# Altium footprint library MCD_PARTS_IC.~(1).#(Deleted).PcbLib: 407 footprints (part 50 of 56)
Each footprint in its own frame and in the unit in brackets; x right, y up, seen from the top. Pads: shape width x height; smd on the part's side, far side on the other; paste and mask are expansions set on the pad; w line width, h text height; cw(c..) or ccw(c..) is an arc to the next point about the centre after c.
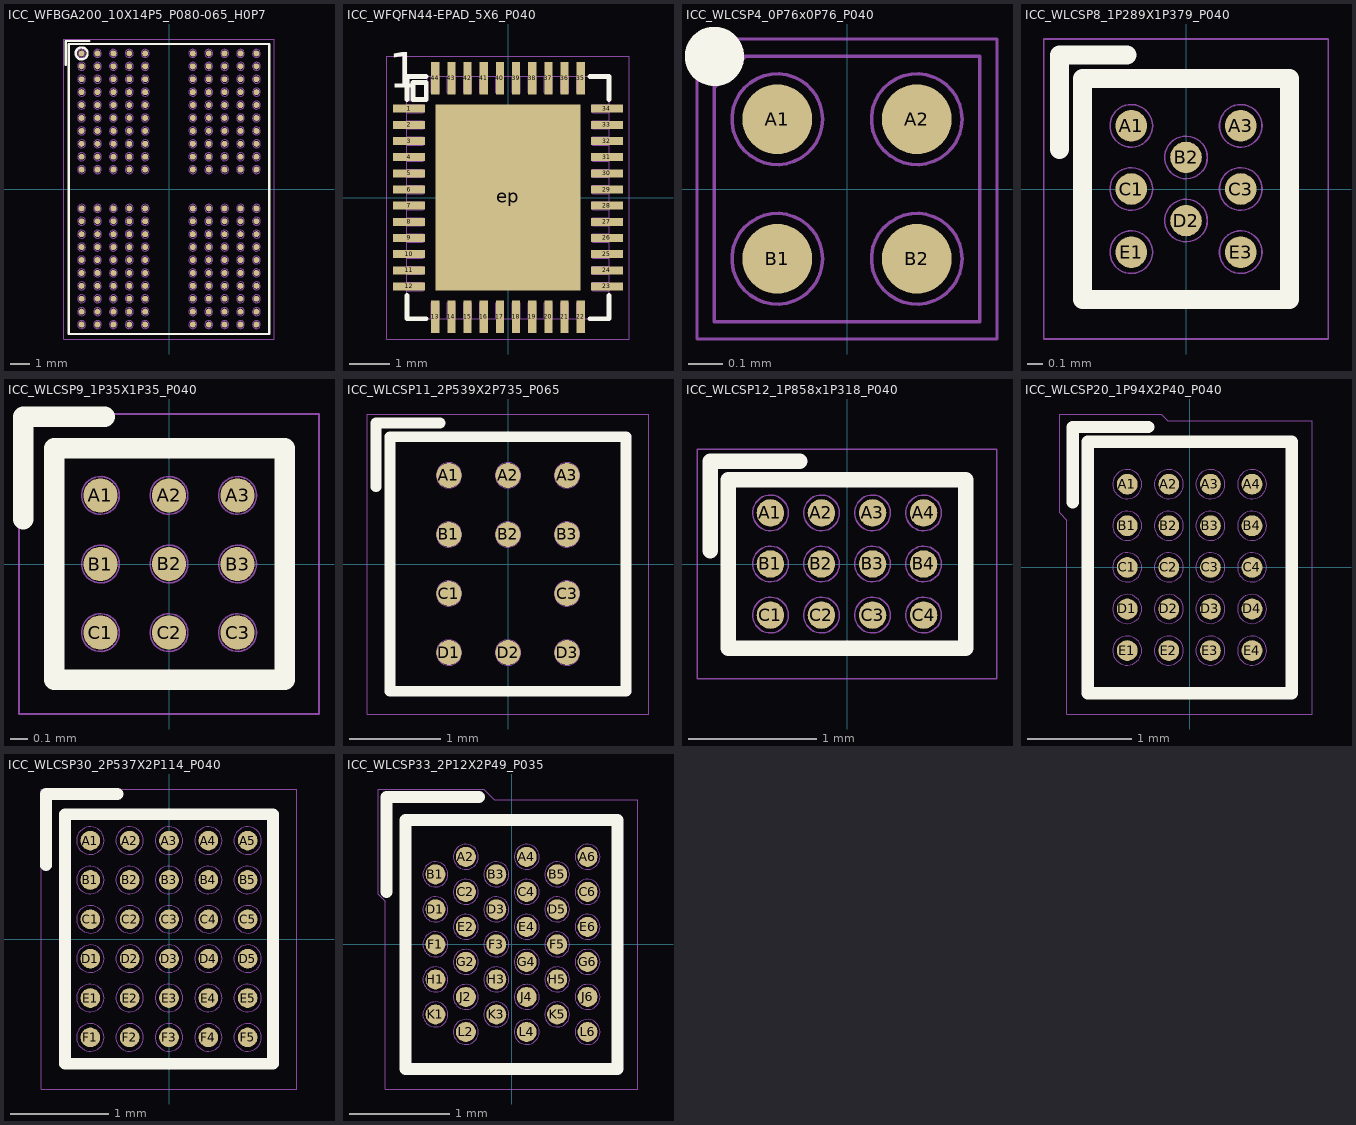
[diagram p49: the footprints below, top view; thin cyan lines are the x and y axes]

## ICC_WFBGA200_10X14P5_P080-065_H0P7 [mm] "MCD-02297"
height 0.8
pads (200):
  round 0.3 smd mask+0.05: A1(-4.4,6.825) A2(-3.6,6.825) A3(-2.8,6.825) A4(-2,6.825) A5(-1.2,6.825) A8(1.2,6.825) A9(2,6.825) A10(2.8,6.825) A11(3.6,6.825) A12(4.4,6.825) AA1(-4.4,-6.175) AA2(-3.6,-6.175) AA3(-2.8,-6.175) AA4(-2,-6.175) AA5(-1.2,-6.175) AA8(1.2,-6.175) AA9(2,-6.175) AA10(2.8,-6.175) AA11(3.6,-6.175) AA12(4.4,-6.175) AB1(-4.4,-6.825) AB2(-3.6,-6.825) AB3(-2.8,-6.825) AB4(-2,-6.825) AB5(-1.2,-6.825) AB8(1.2,-6.825) AB9(2,-6.825) AB10(2.8,-6.825) AB11(3.6,-6.825) AB12(4.4,-6.825) B1(-4.4,6.175) B2(-3.6,6.175) B3(-2.8,6.175) B4(-2,6.175) B5(-1.2,6.175) B8(1.2,6.175) B9(2,6.175) B10(2.8,6.175) B11(3.6,6.175) B12(4.4,6.175) C1(-4.4,5.525) C2(-3.6,5.525) C3(-2.8,5.525) C4(-2,5.525) C5(-1.2,5.525) C8(1.2,5.525) C9(2,5.525) C10(2.8,5.525) C11(3.6,5.525) C12(4.4,5.525) D1(-4.4,4.875) D2(-3.6,4.875) D3(-2.8,4.875) D4(-2,4.875) D5(-1.2,4.875) D8(1.2,4.875) D9(2,4.875) D10(2.8,4.875) D11(3.6,4.875) D12(4.4,4.875) E1(-4.4,4.225) E2(-3.6,4.225) E3(-2.8,4.225) E4(-2,4.225) E5(-1.2,4.225) E8(1.2,4.225) E9(2,4.225) E10(2.8,4.225) E11(3.6,4.225) E12(4.4,4.225) F1(-4.4,3.575) F2(-3.6,3.575) F3(-2.8,3.575) F4(-2,3.575) F5(-1.2,3.575) F8(1.2,3.575) F9(2,3.575) F10(2.8,3.575) F11(3.6,3.575) F12(4.4,3.575) G1(-4.4,2.925) G2(-3.6,2.925) G3(-2.8,2.925) G4(-2,2.925) G5(-1.2,2.925) G8(1.2,2.925) G9(2,2.925) G10(2.8,2.925) G11(3.6,2.925) G12(4.4,2.925) H1(-4.4,2.275) H2(-3.6,2.275) H3(-2.8,2.275) H4(-2,2.275) H5(-1.2,2.275) H8(1.2,2.275) H9(2,2.275) H10(2.8,2.275) H11(3.6,2.275) H12(4.4,2.275) J1(-4.4,1.625) J2(-3.6,1.625) J3(-2.8,1.625) J4(-2,1.625) J5(-1.2,1.625) J8(1.2,1.625) J9(2,1.625) J10(2.8,1.625) J11(3.6,1.625) J12(4.4,1.625) K1(-4.4,0.975) K2(-3.6,0.975) K3(-2.8,0.975) K4(-2,0.975) K5(-1.2,0.975) K8(1.2,0.975) K9(2,0.975) K10(2.8,0.975) K11(3.6,0.975) K12(4.4,0.975) N1(-4.4,-0.975) N2(-3.6,-0.975) N3(-2.8,-0.975) N4(-2,-0.975) N5(-1.2,-0.975) N8(1.2,-0.975) N9(2,-0.975) N10(2.8,-0.975) N11(3.6,-0.975) N12(4.4,-0.975) P1(-4.4,-1.625) P2(-3.6,-1.625) P3(-2.8,-1.625) P4(-2,-1.625) P5(-1.2,-1.625) P8(1.2,-1.625) P9(2,-1.625) P10(2.8,-1.625) P11(3.6,-1.625) P12(4.4,-1.625) R1(-4.4,-2.275) R2(-3.6,-2.275) R3(-2.8,-2.275) R4(-2,-2.275) R5(-1.2,-2.275) R8(1.2,-2.275) R9(2,-2.275) R10(2.8,-2.275) R11(3.6,-2.275) R12(4.4,-2.275) T1(-4.4,-2.925) T2(-3.6,-2.925) T3(-2.8,-2.925) T4(-2,-2.925) T5(-1.2,-2.925) T8(1.2,-2.925) T9(2,-2.925) T10(2.8,-2.925) T11(3.6,-2.925) T12(4.4,-2.925) U1(-4.4,-3.575) U2(-3.6,-3.575) U3(-2.8,-3.575) U4(-2,-3.575) U5(-1.2,-3.575) U8(1.2,-3.575) U9(2,-3.575) U10(2.8,-3.575) U11(3.6,-3.575) U12(4.4,-3.575) V1(-4.4,-4.225) V2(-3.6,-4.225) V3(-2.8,-4.225) V4(-2,-4.225) V5(-1.2,-4.225) V8(1.2,-4.225) V9(2,-4.225) V10(2.8,-4.225) V11(3.6,-4.225) V12(4.4,-4.225) W1(-4.4,-4.875) W2(-3.6,-4.875) W3(-2.8,-4.875) W4(-2,-4.875) W5(-1.2,-4.875) W8(1.2,-4.875) W9(2,-4.875) W10(2.8,-4.875) W11(3.6,-4.875) W12(4.4,-4.875) Y1(-4.4,-5.525) Y2(-3.6,-5.525) Y3(-2.8,-5.525) Y4(-2,-5.525) Y5(-1.2,-5.525) Y8(1.2,-5.525) Y9(2,-5.525) Y10(2.8,-5.525) Y11(3.6,-5.525) Y12(4.4,-5.525)
Top Overlay:
  circle w0.12: c-4.4,6.825 r0.3
  lines w0.12: -5.2,6.25 -5.2,7.45 -4,7.45 ; -5.05,-7.3 5.05,-7.3 5.05,7.3 -5.05,7.3 -5.05,-7.3
M14-Top Assembly:
  drawing of 204 lines, arcs and shapes, not listed
  text "A1" at -4.65,6.65 h0.4
  text "'.Designator'" at -2,-0.5 h0.75
  text "A8" at 0.875,6.65 h0.4
  text "A12" at 3.925,6.65 h0.4
  text "K1" at -4.625,0.8 h0.4
  text "K5" at -1.5,0.8 h0.4
  text "K8" at 0.875,0.8 h0.4
  text "K12" at 3.95,0.8 h0.4
  text "N1" at -4.65,-1.15 h0.4
  text "N5" at -1.525,-1.15 h0.4
  text "N8" at 0.875,-1.15 h0.4
  text "N12" at 3.925,-1.15 h0.4
  text "AB1" at -4.825,-7 h0.4
  text "AB5" at -1.7,-7 h0.4
  text "AB8" at 0.7,-7 h0.4
  text "AB12" at 3.675,-7 h0.4
  text "A5" at -1.525,6.65 h0.4
M16-Top Courtyard:
  lines w0.01: -5.3,-7.55 -5.3,7.55 5.3,7.55 5.3,-7.55 -5.3,-7.55
3D body: height 0.81, standoff 0.8, extent -4.697,6.526 -4.1,7.125
3D body: height 0.36, standoff -0.04, extent 4.201,-2.472 4.6,-2.078
3D body: height 0.36, standoff -0.04, extent 3.401,-2.472 3.8,-2.078
3D body: height 0.36, standoff -0.04, extent 1.001,-2.472 1.4,-2.078
3D body: height 0.36, standoff -0.04, extent 1.801,-2.472 2.2,-2.078
3D body: height 0.36, standoff -0.04, extent 2.601,-2.472 3,-2.078
3D body: height 0.36, standoff -0.04, extent -4.599,-2.472 -4.2,-2.078
3D body: height 0.36, standoff -0.04, extent -3.799,-2.472 -3.4,-2.078
3D body: height 0.36, standoff -0.04, extent -2.999,-2.472 -2.6,-2.078
3D body: height 0.36, standoff -0.04, extent -2.199,-2.472 -1.8,-2.078
3D body: height 0.36, standoff -0.04, extent -1.399,-2.472 -1,-2.078
3D body: height 0.36, standoff -0.04, extent 4.201,-1.822 4.6,-1.428
3D body: height 0.36, standoff -0.04, extent 3.401,-1.822 3.8,-1.428
3D body: height 0.36, standoff -0.04, extent 1.001,-1.822 1.4,-1.428
3D body: height 0.36, standoff -0.04, extent 1.801,-1.822 2.2,-1.428
3D body: height 0.36, standoff -0.04, extent 2.601,-1.822 3,-1.428
3D body: height 0.36, standoff -0.04, extent -4.599,-1.822 -4.2,-1.428
3D body: height 0.36, standoff -0.04, extent -3.799,-1.822 -3.4,-1.428
3D body: height 0.36, standoff -0.04, extent -2.999,-1.822 -2.6,-1.428
3D body: height 0.36, standoff -0.04, extent -2.199,-1.822 -1.8,-1.428
3D body: height 0.36, standoff -0.04, extent -1.399,-1.822 -1,-1.428
3D body: height 0.36, standoff -0.04, extent 4.201,-1.172 4.6,-0.778
3D body: height 0.36, standoff -0.04, extent 3.401,-1.172 3.8,-0.778
3D body: height 0.36, standoff -0.04, extent 1.001,-1.172 1.4,-0.778
3D body: height 0.36, standoff -0.04, extent 1.801,-1.172 2.2,-0.778
3D body: height 0.36, standoff -0.04, extent 2.601,-1.172 3,-0.778
3D body: height 0.36, standoff -0.04, extent -4.599,-1.172 -4.2,-0.778
3D body: height 0.36, standoff -0.04, extent -3.799,-1.172 -3.4,-0.778
3D body: height 0.36, standoff -0.04, extent -2.999,-1.172 -2.6,-0.778
3D body: height 0.36, standoff -0.04, extent -2.199,-1.172 -1.8,-0.778
3D body: height 0.36, standoff -0.04, extent -1.399,-1.172 -1,-0.778
3D body: height 0.36, standoff -0.04, extent 3.401,0.778 3.8,1.172
3D body: height 0.36, standoff -0.04, extent 1.001,0.778 1.4,1.172
3D body: height 0.36, standoff -0.04, extent 1.801,0.778 2.2,1.172
3D body: height 0.36, standoff -0.04, extent 2.601,0.778 3,1.172
3D body: height 0.36, standoff -0.04, extent -4.599,0.778 -4.2,1.172
3D body: height 0.36, standoff -0.04, extent -3.799,0.778 -3.4,1.172
3D body: height 0.36, standoff -0.04, extent -2.999,0.778 -2.6,1.172
3D body: height 0.36, standoff -0.04, extent -2.199,0.778 -1.8,1.172
3D body: height 0.36, standoff -0.04, extent -1.399,0.778 -1,1.172
3D body: height 0.36, standoff -0.04, extent 3.401,1.428 3.8,1.822
3D body: height 0.36, standoff -0.04, extent 1.001,1.428 1.4,1.822
3D body: height 0.36, standoff -0.04, extent 1.801,1.428 2.2,1.822
3D body: height 0.36, standoff -0.04, extent 2.601,1.428 3,1.822
3D body: height 0.36, standoff -0.04, extent -4.599,1.428 -4.2,1.822
3D body: height 0.36, standoff -0.04, extent -3.799,1.428 -3.4,1.822
3D body: height 0.36, standoff -0.04, extent -2.999,1.428 -2.6,1.822
3D body: height 0.36, standoff -0.04, extent -2.199,1.428 -1.8,1.822
3D body: height 0.36, standoff -0.04, extent -1.399,1.428 -1,1.822
3D body: height 0.36, standoff -0.04, extent 3.401,2.078 3.8,2.472
3D body: height 0.36, standoff -0.04, extent 1.001,2.078 1.4,2.472
3D body: height 0.36, standoff -0.04, extent 1.801,2.078 2.2,2.472
3D body: height 0.36, standoff -0.04, extent 2.601,2.078 3,2.472
3D body: height 0.36, standoff -0.04, extent -4.599,2.078 -4.2,2.472
3D body: height 0.36, standoff -0.04, extent -3.799,2.078 -3.4,2.472
3D body: height 0.36, standoff -0.04, extent -2.999,2.078 -2.6,2.472
3D body: height 0.36, standoff -0.04, extent -2.199,2.078 -1.8,2.472
3D body: height 0.36, standoff -0.04, extent -1.399,2.078 -1,2.472
3D body: height 0.36, standoff -0.04, extent 3.401,2.728 3.8,3.122
3D body: height 0.36, standoff -0.04, extent 1.001,2.728 1.4,3.122
3D body: height 0.36, standoff -0.04, extent 1.801,2.728 2.2,3.122
3D body: height 0.36, standoff -0.04, extent 2.601,2.728 3,3.122
3D body: height 0.36, standoff -0.04, extent -4.599,2.728 -4.2,3.122
3D body: height 0.36, standoff -0.04, extent -3.799,2.728 -3.4,3.122
3D body: height 0.36, standoff -0.04, extent -2.999,2.728 -2.6,3.122
3D body: height 0.36, standoff -0.04, extent -2.199,2.728 -1.8,3.122
3D body: height 0.36, standoff -0.04, extent -1.399,2.728 -1,3.122
3D body: height 0.36, standoff -0.04, extent -4.599,3.378 -4.2,3.772
3D body: height 0.36, standoff -0.04, extent -3.799,3.378 -3.4,3.772
3D body: height 0.36, standoff -0.04, extent -2.999,3.378 -2.6,3.772
3D body: height 0.36, standoff -0.04, extent -2.199,3.378 -1.8,3.772
3D body: height 0.36, standoff -0.04, extent -1.399,3.378 -1,3.772
3D body: height 0.36, standoff -0.04, extent 4.201,4.028 4.6,4.422
3D body: height 0.36, standoff -0.04, extent 3.401,4.028 3.8,4.422
3D body: height 0.36, standoff -0.04, extent 1.001,4.028 1.4,4.422
3D body: height 0.36, standoff -0.04, extent 1.801,4.028 2.2,4.422
3D body: height 0.36, standoff -0.04, extent 2.601,4.028 3,4.422
3D body: height 0.36, standoff -0.04, extent -4.599,4.028 -4.2,4.422
3D body: height 0.36, standoff -0.04, extent -3.799,4.028 -3.4,4.422
3D body: height 0.36, standoff -0.04, extent -2.999,4.028 -2.6,4.422
3D body: height 0.36, standoff -0.04, extent -2.199,4.028 -1.8,4.422
3D body: height 0.36, standoff -0.04, extent -1.399,4.028 -1,4.422
3D body: height 0.36, standoff -0.04, extent 4.201,4.678 4.6,5.072
3D body: height 0.36, standoff -0.04, extent 3.401,4.678 3.8,5.072
3D body: height 0.36, standoff -0.04, extent 1.001,4.678 1.4,5.072
3D body: height 0.36, standoff -0.04, extent 1.801,4.678 2.2,5.072
3D body: height 0.36, standoff -0.04, extent 2.601,4.678 3,5.072
3D body: height 0.36, standoff -0.04, extent -4.599,4.678 -4.2,5.072
3D body: height 0.36, standoff -0.04, extent -3.799,4.678 -3.4,5.072
3D body: height 0.36, standoff -0.04, extent -2.999,4.678 -2.6,5.072
3D body: height 0.36, standoff -0.04, extent -2.199,4.678 -1.8,5.072
3D body: height 0.36, standoff -0.04, extent -1.399,4.678 -1,5.072
3D body: height 0.36, standoff -0.04, extent 4.201,5.328 4.6,5.722
3D body: height 0.36, standoff -0.04, extent 3.401,5.328 3.8,5.722
3D body: height 0.36, standoff -0.04, extent 1.001,5.328 1.4,5.722
3D body: height 0.36, standoff -0.04, extent 1.801,5.328 2.2,5.722
3D body: height 0.36, standoff -0.04, extent 2.601,5.328 3,5.722
3D body: height 0.36, standoff -0.04, extent -4.599,5.328 -4.2,5.722
3D body: height 0.36, standoff -0.04, extent -3.799,5.328 -3.4,5.722
3D body: height 0.36, standoff -0.04, extent -2.999,5.328 -2.6,5.722
3D body: height 0.36, standoff -0.04, extent -2.199,5.328 -1.8,5.722
3D body: height 0.36, standoff -0.04, extent -1.399,5.328 -1,5.722
3D body: height 0.36, standoff -0.04, extent 4.201,5.978 4.6,6.372
3D body: height 0.36, standoff -0.04, extent 3.401,5.978 3.8,6.372
3D body: height 0.36, standoff -0.04, extent 1.001,5.978 1.4,6.372
3D body: height 0.36, standoff -0.04, extent 1.801,5.978 2.2,6.372
3D body: height 0.36, standoff -0.04, extent 2.601,5.978 3,6.372
3D body: height 0.36, standoff -0.04, extent -4.599,5.978 -4.2,6.372
3D body: height 0.36, standoff -0.04, extent -3.799,5.978 -3.4,6.372
3D body: height 0.36, standoff -0.04, extent -2.999,5.978 -2.6,6.372
3D body: height 0.36, standoff -0.04, extent -2.199,5.978 -1.8,6.372
3D body: height 0.36, standoff -0.04, extent -1.399,5.978 -1,6.372
3D body: height 0.36, standoff -0.04, extent -1.399,6.628 -1,7.022
3D body: height 0.36, standoff -0.04, extent -2.199,6.628 -1.8,7.022
3D body: height 0.36, standoff -0.04, extent -2.999,6.628 -2.6,7.022
3D body: height 0.36, standoff -0.04, extent -3.799,6.628 -3.4,7.022
3D body: height 0.36, standoff -0.04, extent -4.599,6.628 -4.2,7.022
3D body: height 0.36, standoff -0.04, extent 2.601,6.628 3,7.022
3D body: height 0.36, standoff -0.04, extent 1.801,6.628 2.2,7.022
3D body: height 0.36, standoff -0.04, extent 1.001,6.628 1.4,7.022
3D body: height 0.36, standoff -0.04, extent 3.401,6.628 3.8,7.022
3D body: height 0.36, standoff -0.04, extent 4.201,6.628 4.6,7.022
3D body: height 0.8, standoff 0.3, extent -5.05,-7.3 5.05,7.3
3D body: height 0.36, standoff -0.04, extent -1.399,-3.122 -1,-2.728
3D body: height 0.36, standoff -0.04, extent -2.199,-3.122 -1.8,-2.728
3D body: height 0.36, standoff -0.04, extent -2.999,-3.122 -2.6,-2.728
3D body: height 0.36, standoff -0.04, extent -3.799,-3.122 -3.4,-2.728
3D body: height 0.36, standoff -0.04, extent -4.599,-3.122 -4.2,-2.728
3D body: height 0.36, standoff -0.04, extent 2.601,-3.122 3,-2.728
3D body: height 0.36, standoff -0.04, extent 1.801,-3.122 2.2,-2.728
3D body: height 0.36, standoff -0.04, extent 1.001,-3.122 1.4,-2.728
3D body: height 0.36, standoff -0.04, extent 3.401,-3.122 3.8,-2.728
3D body: height 0.36, standoff -0.04, extent 4.201,-3.122 4.6,-2.728
3D body: height 0.36, standoff -0.04, extent -1.399,-3.772 -1,-3.378
3D body: height 0.36, standoff -0.04, extent -2.199,-3.772 -1.8,-3.378
3D body: height 0.36, standoff -0.04, extent -2.999,-3.772 -2.6,-3.378
3D body: height 0.36, standoff -0.04, extent -3.799,-3.772 -3.4,-3.378
3D body: height 0.36, standoff -0.04, extent -4.599,-3.772 -4.2,-3.378
3D body: height 0.36, standoff -0.04, extent 2.601,-3.772 3,-3.378
3D body: height 0.36, standoff -0.04, extent 1.801,-3.772 2.2,-3.378
3D body: height 0.36, standoff -0.04, extent 1.001,-3.772 1.4,-3.378
3D body: height 0.36, standoff -0.04, extent 3.401,-3.772 3.8,-3.378
3D body: height 0.36, standoff -0.04, extent 4.201,-3.772 4.6,-3.378
3D body: height 0.36, standoff -0.04, extent 4.201,3.378 4.6,3.772
3D body: height 0.36, standoff -0.04, extent 3.401,3.378 3.8,3.772
3D body: height 0.36, standoff -0.04, extent 1.001,3.378 1.4,3.772
3D body: height 0.36, standoff -0.04, extent 1.801,3.378 2.2,3.772
3D body: height 0.36, standoff -0.04, extent 2.601,3.378 3,3.772
3D body: height 0.36, standoff -0.04, extent 4.201,0.778 4.6,1.172
3D body: height 0.36, standoff -0.04, extent 4.201,1.428 4.6,1.822
3D body: height 0.36, standoff -0.04, extent 4.201,2.078 4.6,2.472
3D body: height 0.36, standoff -0.04, extent 4.201,2.728 4.6,3.122
3D body: height 0.36, standoff -0.04, extent -1.399,-4.422 -1,-4.028
3D body: height 0.36, standoff -0.04, extent -2.199,-4.422 -1.8,-4.028
3D body: height 0.36, standoff -0.04, extent -2.999,-4.422 -2.6,-4.028
3D body: height 0.36, standoff -0.04, extent -3.799,-4.422 -3.4,-4.028
3D body: height 0.36, standoff -0.04, extent -4.599,-4.422 -4.2,-4.028
3D body: height 0.36, standoff -0.04, extent 2.601,-4.422 3,-4.028
3D body: height 0.36, standoff -0.04, extent 1.801,-4.422 2.2,-4.028
3D body: height 0.36, standoff -0.04, extent 1.001,-4.422 1.4,-4.028
3D body: height 0.36, standoff -0.04, extent 3.401,-4.422 3.8,-4.028
3D body: height 0.36, standoff -0.04, extent 4.201,-4.422 4.6,-4.028
3D body: height 0.36, standoff -0.04, extent -1.399,-5.072 -1,-4.678
3D body: height 0.36, standoff -0.04, extent -2.199,-5.072 -1.8,-4.678
3D body: height 0.36, standoff -0.04, extent -2.999,-5.072 -2.6,-4.678
3D body: height 0.36, standoff -0.04, extent -3.799,-5.072 -3.4,-4.678
3D body: height 0.36, standoff -0.04, extent -4.599,-5.072 -4.2,-4.678
3D body: height 0.36, standoff -0.04, extent 2.601,-5.072 3,-4.678
3D body: height 0.36, standoff -0.04, extent 1.801,-5.072 2.2,-4.678
3D body: height 0.36, standoff -0.04, extent 1.001,-5.072 1.4,-4.678
3D body: height 0.36, standoff -0.04, extent 3.401,-5.072 3.8,-4.678
3D body: height 0.36, standoff -0.04, extent 4.201,-5.072 4.6,-4.678
3D body: height 0.36, standoff -0.04, extent -1.399,-5.722 -1,-5.328
3D body: height 0.36, standoff -0.04, extent -2.199,-5.722 -1.8,-5.328
3D body: height 0.36, standoff -0.04, extent -2.999,-5.722 -2.6,-5.328
3D body: height 0.36, standoff -0.04, extent -3.799,-5.722 -3.4,-5.328
3D body: height 0.36, standoff -0.04, extent -4.599,-5.722 -4.2,-5.328
3D body: height 0.36, standoff -0.04, extent 2.601,-5.722 3,-5.328
3D body: height 0.36, standoff -0.04, extent 1.801,-5.722 2.2,-5.328
3D body: height 0.36, standoff -0.04, extent 1.001,-5.722 1.4,-5.328
3D body: height 0.36, standoff -0.04, extent 3.401,-5.722 3.8,-5.328
3D body: height 0.36, standoff -0.04, extent 4.201,-5.722 4.6,-5.328
3D body: height 0.36, standoff -0.04, extent -1.399,-6.372 -1,-5.978
3D body: height 0.36, standoff -0.04, extent -2.199,-6.372 -1.8,-5.978
3D body: height 0.36, standoff -0.04, extent -2.999,-6.372 -2.6,-5.978
3D body: height 0.36, standoff -0.04, extent -3.799,-6.372 -3.4,-5.978
3D body: height 0.36, standoff -0.04, extent -4.599,-6.372 -4.2,-5.978
3D body: height 0.36, standoff -0.04, extent 2.601,-6.372 3,-5.978
3D body: height 0.36, standoff -0.04, extent 1.801,-6.372 2.2,-5.978
3D body: height 0.36, standoff -0.04, extent 1.001,-6.372 1.4,-5.978
3D body: height 0.36, standoff -0.04, extent 3.401,-6.372 3.8,-5.978
3D body: height 0.36, standoff -0.04, extent 4.201,-6.372 4.6,-5.978
3D body: height 0.36, standoff -0.04, extent -1.399,-7.022 -1,-6.628
3D body: height 0.36, standoff -0.04, extent -2.199,-7.022 -1.8,-6.628
3D body: height 0.36, standoff -0.04, extent -2.999,-7.022 -2.6,-6.628
3D body: height 0.36, standoff -0.04, extent -3.799,-7.022 -3.4,-6.628
3D body: height 0.36, standoff -0.04, extent -4.599,-7.022 -4.2,-6.628
3D body: height 0.36, standoff -0.04, extent 2.601,-7.022 3,-6.628
3D body: height 0.36, standoff -0.04, extent 1.801,-7.022 2.2,-6.628
3D body: height 0.36, standoff -0.04, extent 1.001,-7.022 1.4,-6.628
3D body: height 0.36, standoff -0.04, extent 3.401,-7.022 3.8,-6.628
3D body: height 0.36, standoff -0.04, extent 4.201,-7.022 4.6,-6.628

## ICC_WFQFN44-EPAD_5X6_P040 [mm]
height 0.8
pads (45):
  rect 0.8x0.2 smd mask+0.05: 1(-2.45,2.2) 2(-2.45,1.8) 3(-2.45,1.4) 4(-2.45,1) 5(-2.45,0.6) 6(-2.45,0.2) 7(-2.45,-0.2) 8(-2.45,-0.6) 9(-2.45,-1) 10(-2.45,-1.4) 11(-2.45,-1.8) 12(-2.45,-2.2) 23(2.45,-2.2) 24(2.45,-1.8) 25(2.45,-1.4) 26(2.45,-1) 27(2.45,-0.6) 28(2.45,-0.2) 29(2.45,0.2) 30(2.45,0.6) 31(2.45,1) 32(2.45,1.4) 33(2.45,1.8) 34(2.45,2.2)
  rect 0.2x0.8 smd mask+0.05: 13(-1.8,-2.95) 14(-1.4,-2.95) 15(-1,-2.95) 16(-0.6,-2.95) 17(-0.2,-2.95) 18(0.2,-2.95) 19(0.6,-2.95) 20(1,-2.95) 21(1.4,-2.95) 22(1.8,-2.95) 35(1.8,2.95) 36(1.4,2.95) 37(1,2.95) 38(0.6,2.95) 39(0.2,2.95) 40(-0.2,2.95) 41(-0.6,2.95) 42(-1,2.95) 43(-1.4,2.95) 44(-1.8,2.95)
  rect 3.6x4.6 smd paste-1.8 mask+0.05: ep(0,0)
Top Overlay:
  lines w0.12: -2.5,-2.425 -2.5,-3 -2.025,-3 ; -2.5,2.425 -2.5,3 -2.025,3 ; 2.025,-3 2.5,-3 2.5,-2.425 ; 2.025,3 2.5,3 2.5,2.425 ; -2.35,2.425 -2.025,2.425 -2.025,2.85 -2.35,2.85 -2.35,2.425
  text "1" at -2.95,2.425 h1.5
Top Paste:
  rectangle: 1.3,-2.2 1.7,-1.825
  rectangle: 1.3,-1.625 1.7,-1.25
  rectangle: 1.3,-1.05 1.7,-0.675
  rectangle: 1.3,-0.475 1.7,-0.1
  rectangle: 0.7,-0.475 1.1,-0.1
  rectangle: 0.7,-1.05 1.1,-0.675
  rectangle: 0.7,-1.625 1.1,-1.25
  rectangle: 0.7,-2.2 1.1,-1.825
  rectangle: 0.1,-0.475 0.5,-0.1
  rectangle: 0.1,-1.05 0.5,-0.675
  rectangle: 0.1,-1.625 0.5,-1.25
  rectangle: 0.1,-2.2 0.5,-1.825
  rectangle: -0.5,-2.2 -0.1,-1.825
  rectangle: -0.5,-1.625 -0.1,-1.25
  rectangle: -0.5,-1.05 -0.1,-0.675
  rectangle: -0.5,-0.475 -0.1,-0.1
  rectangle: -1.1,-0.475 -0.7,-0.1
  rectangle: -1.1,-1.05 -0.7,-0.675
  rectangle: -1.1,-1.625 -0.7,-1.25
  rectangle: -1.1,-2.2 -0.7,-1.825
  rectangle: -1.7,-0.475 -1.3,-0.1
  rectangle: -1.7,-1.05 -1.3,-0.675
  rectangle: -1.7,-1.625 -1.3,-1.25
  rectangle: -1.7,-2.2 -1.3,-1.825
  rectangle: 1.3,0.1 1.7,0.475
  rectangle: 1.3,0.675 1.7,1.05
  rectangle: 1.3,1.25 1.7,1.625
  rectangle: 1.3,1.825 1.7,2.2
  rectangle: 0.7,1.825 1.1,2.2
  rectangle: 0.7,1.25 1.1,1.625
  rectangle: 0.7,0.675 1.1,1.05
  rectangle: 0.7,0.1 1.1,0.475
  rectangle: 0.1,1.825 0.5,2.2
  rectangle: 0.1,1.25 0.5,1.625
  rectangle: 0.1,0.675 0.5,1.05
  rectangle: 0.1,0.1 0.5,0.475
  rectangle: -1.7,0.1 -1.3,0.475
  rectangle: -1.7,0.675 -1.3,1.05
  rectangle: -1.7,1.25 -1.3,1.625
  rectangle: -1.7,1.825 -1.3,2.2
  rectangle: -1.1,0.1 -0.7,0.475
  rectangle: -1.1,0.675 -0.7,1.05
  rectangle: -1.1,1.25 -0.7,1.625
  rectangle: -1.1,1.825 -0.7,2.2
  rectangle: -0.5,1.825 -0.1,2.2
  rectangle: -0.5,1.25 -0.1,1.625
  rectangle: -0.5,0.675 -0.1,1.05
  rectangle: -0.5,0.1 -0.1,0.475
M14-Top Assembly:
  lines w0.01: -2.5,-2.3 -2.1,-2.3 -2.1,-2.1 -2.5,-2.1 ; -2.5,-1.9 -2.1,-1.9 -2.1,-1.7 -2.5,-1.7 ; -2.5,-1.5 -2.1,-1.5 -2.1,-1.3 -2.5,-1.3 ; -2.5,-1.1 -2.1,-1.1 -2.1,-0.9 -2.5,-0.9 ; -2.5,-0.7 -2.1,-0.7 -2.1,-0.5 -2.5,-0.5 ; -2.5,-0.3 -2.1,-0.3 -2.1,-0.1 -2.5,-0.1 ; -2.5,0.1 -2.1,0.1 -2.1,0.3 -2.5,0.3 ; -2.5,0.5 -2.1,0.5 -2.1,0.7 -2.5,0.7 ; -2.5,0.9 -2.1,0.9 -2.1,1.1 -2.5,1.1 ; -2.5,1.3 -2.1,1.3 -2.1,1.5 -2.5,1.5 ; -2.5,1.7 -2.1,1.7 -2.1,1.9 -2.5,1.9 ; -2.5,2.1 -2.1,2.1 -2.1,2.3 -2.5,2.3 ; -1.9,-3 -1.9,-2.6 -1.7,-2.6 -1.7,-3 ; -1.9,3 -1.9,2.6 -1.7,2.6 -1.7,3 ; -1.5,-3 -1.5,-2.6 -1.3,-2.6 -1.3,-3 ; -1.5,3 -1.5,2.6 -1.3,2.6 -1.3,3 ; -1.1,-3 -1.1,-2.6 -0.9,-2.6 -0.9,-3 ; -1.1,3 -1.1,2.6 -0.9,2.6 -0.9,3 ; -0.7,-3 -0.7,-2.6 -0.5,-2.6 -0.5,-3 ; -0.7,3 -0.7,2.6 -0.5,2.6 -0.5,3 ; -0.3,-3 -0.3,-2.6 -0.1,-2.6 -0.1,-3 ; -0.3,3 -0.3,2.6 -0.1,2.6 -0.1,3 ; 0.1,-3 0.1,-2.6 0.3,-2.6 0.3,-3 ; 0.1,3 0.1,2.6 0.3,2.6 0.3,3 ; 0.5,-3 0.5,-2.6 0.7,-2.6 0.7,-3 ; 0.5,3 0.5,2.6 0.7,2.6 0.7,3 ; 0.9,-3 0.9,-2.6 1.1,-2.6 1.1,-3 ; 0.9,3 0.9,2.6 1.1,2.6 1.1,3 ; 1.3,-3 1.3,-2.6 1.5,-2.6 1.5,-3 ; 1.3,3 1.3,2.6 1.5,2.6 1.5,3 ; 1.7,-3 1.7,-2.6 1.9,-2.6 1.9,-3 ; 1.7,3 1.7,2.6 1.9,2.6 1.9,3 ; 2.5,-2.3 2.1,-2.3 2.1,-2.1 2.5,-2.1 ; 2.5,-1.9 2.1,-1.9 2.1,-1.7 2.5,-1.7 ; 2.5,-1.5 2.1,-1.5 2.1,-1.3 2.5,-1.3 ; 2.5,-1.1 2.1,-1.1 2.1,-0.9 2.5,-0.9 ; 2.5,-0.7 2.1,-0.7 2.1,-0.5 2.5,-0.5 ; 2.5,-0.3 2.1,-0.3 2.1,-0.1 2.5,-0.1 ; 2.5,0.1 2.1,0.1 2.1,0.3 2.5,0.3 ; 2.5,0.5 2.1,0.5 2.1,0.7 2.5,0.7 ; 2.5,0.9 2.1,0.9 2.1,1.1 2.5,1.1 ; 2.5,1.3 2.1,1.3 2.1,1.5 2.5,1.5 ; 2.5,1.7 2.1,1.7 2.1,1.9 2.5,1.9 ; 2.5,2.1 2.1,2.1 2.1,2.3 2.5,2.3 ; -2.5,-3 2.5,-3 2.5,3 -2.5,3 -2.5,-3 ; -2.45,2.4 -2.45,2.95 -2,2.95 -2,2.4 -2.45,2.4 ; -1.75,-2.25 -1.75,2 -1.5,2.25 1.75,2.25 1.75,-2.25 -1.75,-2.25
  text "'.Designator'" at -2,0.5 h0.75
  text "1" at -2.675,2.05 h0.5
  text "12" at -2.95,-2.375 h0.5
  text "13" at -2.02,-3.36 h0.5
  text "22" at 1.56,-3.36 h0.5
  text "23" at 2.525,-2.35 h0.5
  text "34" at 2.525,2.05 h0.5
  text "35" at 1.58,3.06 h0.5
  text "44" at -2.04,3.05 h0.5
  text "ep" at -0.7,-0.2 h1.5
M16-Top Courtyard:
  lines w0.01: -3,-3.5 -3,2.35 -3,3.5 3,3.5 3,-3.5 -2.975,-3.5 -3,-3.5
3D body: height 0.8, standoff 0.02, extent -2.5,-3 2.5,3
3D body: height 0.02, standoff 0, extent -2.5,2.1 -2.1,2.3
3D body: height 0.02, standoff 0, extent -2.5,1.7 -2.1,1.9
3D body: height 0.02, standoff 0, extent -2.5,1.3 -2.1,1.5
3D body: height 0.02, standoff 0, extent -2.5,0.9 -2.1,1.1
3D body: height 0.02, standoff 0, extent -2.5,0.5 -2.1,0.7
3D body: height 0.02, standoff 0, extent -2.5,0.1 -2.1,0.3
3D body: height 0.02, standoff 0, extent -2.5,-0.3 -2.1,-0.1
3D body: height 0.02, standoff 0, extent -2.5,-0.7 -2.1,-0.5
3D body: height 0.02, standoff 0, extent -2.5,-1.1 -2.1,-0.9
3D body: height 0.02, standoff 0, extent -2.5,-1.5 -2.1,-1.3
3D body: height 0.02, standoff 0, extent -2.5,-1.9 -2.1,-1.7
3D body: height 0.02, standoff 0, extent -2.5,-2.3 -2.1,-2.1
3D body: height 0.02, standoff 0, extent -1.9,-3 -1.7,-2.6
3D body: height 0.02, standoff 0, extent -1.5,-3 -1.3,-2.6
3D body: height 0.02, standoff 0, extent -1.1,-3 -0.9,-2.6
3D body: height 0.02, standoff 0, extent -0.7,-3 -0.5,-2.6
3D body: height 0.02, standoff 0, extent -0.3,-3 -0.1,-2.6
3D body: height 0.02, standoff 0, extent 0.1,-3 0.3,-2.6
3D body: height 0.02, standoff 0, extent 0.5,-3 0.7,-2.6
3D body: height 0.02, standoff 0, extent 0.9,-3 1.1,-2.6
3D body: height 0.02, standoff 0, extent 1.3,-3 1.5,-2.6
3D body: height 0.02, standoff 0, extent 1.7,-3 1.9,-2.6
3D body: height 0.02, standoff 0, extent 2.1,-2.3 2.5,-2.1
3D body: height 0.02, standoff 0, extent 2.1,-1.9 2.5,-1.7
3D body: height 0.02, standoff 0, extent 2.1,-1.5 2.5,-1.3
3D body: height 0.02, standoff 0, extent 2.1,-1.1 2.5,-0.9
3D body: height 0.02, standoff 0, extent 2.1,-0.7 2.5,-0.5
3D body: height 0.02, standoff 0, extent 2.1,-0.3 2.5,-0.1
3D body: height 0.02, standoff 0, extent 2.1,0.1 2.5,0.3
3D body: height 0.02, standoff 0, extent 2.1,0.5 2.5,0.7
3D body: height 0.02, standoff 0, extent 2.1,0.9 2.5,1.1
3D body: height 0.02, standoff 0, extent 2.1,1.3 2.5,1.5
3D body: height 0.02, standoff 0, extent 2.1,1.7 2.5,1.9
3D body: height 0.02, standoff 0, extent 2.1,2.1 2.5,2.3
3D body: height 0.02, standoff 0, extent 1.7,2.6 1.9,3
3D body: height 0.02, standoff 0, extent 1.3,2.6 1.5,3
3D body: height 0.02, standoff 0, extent 0.9,2.6 1.1,3
3D body: height 0.02, standoff 0, extent 0.5,2.6 0.7,3
3D body: height 0.02, standoff 0, extent 0.1,2.6 0.3,3
3D body: height 0.02, standoff 0, extent -0.3,2.6 -0.1,3
3D body: height 0.02, standoff 0, extent -0.7,2.6 -0.5,3
3D body: height 0.02, standoff 0, extent -1.1,2.6 -0.9,3
3D body: height 0.02, standoff 0, extent -1.5,2.6 -1.3,3
3D body: height 0.02, standoff 0, extent -1.9,2.6 -1.7,3
3D body: height 0.81, standoff 0.8, extent -2.45,2.4 -2,2.95
3D body: height 0.02, standoff 0, extent -1.725,-2.225 1.725,2.225

## ICC_WLCSP4_0P76x0P76_P040 [mm] "MCD-02423"
height 0.63
pads (4):
  round 0.2 smd mask+0.05: A1(-0.2,0.2) A2(0.2,0.2) B1(-0.2,-0.2) B2(0.2,-0.2)
Top Overlay:
  circle w0.12: c-0.38,0.38 r0.025
M14-Top Assembly:
  circle w0.01: c0.2,-0.2 r0.13
  circle w0.01: c-0.2,-0.2 r0.13
  circle w0.01: c-0.2,0.2 r0.13
  circle w0.01: c0.2,0.2 r0.13
  lines w0.01: -0.38,0.29 -0.29,0.38 ; -0.38,-0.38 0.38,-0.38 0.38,0.38 -0.38,0.38 -0.38,-0.38
  text "A1" at -0.315,0.135 h0.2
  text "'.Designator'" at -2,-0.5 h0.75
M16-Top Courtyard:
  lines w0.01: -0.43,-0.43 -0.43,0.43 0.43,0.43 0.43,-0.43 -0.43,-0.43
3D body: height 0.63, standoff 0.27, extent -0.38,-0.38 0.38,0.38
3D body: height 0.27, standoff -0.01, extent -0.331,0.062 -0.06,0.338
3D body: height 0.27, standoff -0.01, extent 0.069,0.062 0.34,0.338
3D body: height 0.27, standoff -0.01, extent -0.331,-0.338 -0.06,-0.062
3D body: height 0.27, standoff -0.01, extent 0.069,-0.338 0.34,-0.062

## ICC_WLCSP8_1P289X1P379_P040 [mm] "MCD-04444"
height 0.58
pads (8):
  round 0.2 smd mask+0.05: A1(-0.346,0.4) A3(0.346,0.4) B2(0,0.2) C1(-0.346,0) C3(0.346,0) D2(0,-0.2) E1(-0.346,-0.4) E3(0.346,-0.4)
Top Overlay:
  lines w0.12: -0.8,0.25 -0.8,0.85 -0.375,0.85 ; -0.654,-0.7 -0.654,0.7 0.654,0.7 0.654,-0.7 -0.654,-0.7
M14-Top Assembly:
  circle w0.01: c0.346,-0.4 r0.135
  circle w0.01: c0,-0.2 r0.135
  circle w0.01: c-0.346,-0.4 r0.135
  circle w0.01: c0.346,0 r0.135
  circle w0.01: c0,0.2 r0.135
  circle w0.01: c-0.346,0 r0.135
  circle w0.01: c0.346,0.4 r0.135
  circle w0.01: c-0.346,0.4 r0.135
  lines w0.01: -0.654,-0.7 0.654,-0.7 0.654,0.7 -0.654,0.7 -0.654,-0.7
  text "'.Designator'" at -2,-0.5 h0.75
  text "A1" at -0.625,0.25 h0.5
M16-Top Courtyard:
  lines w0.01: -0.9,-0.95 0.9,-0.95 0.9,0.95 -0.9,0.95 -0.9,-0.95
3D body: height 0.27, standoff 0, extent -0.482,-0.535 -0.211,-0.265
3D body: height 0.27, standoff 0, extent 0.211,-0.535 0.482,-0.265
3D body: height 0.27, standoff 0, extent 0.211,-0.135 0.482,0.135
3D body: height 0.27, standoff 0, extent -0.482,-0.135 -0.211,0.135
3D body: height 0.27, standoff 0, extent -0.135,0.065 0.135,0.335
3D body: height 0.59, standoff 0.58, extent -0.55,0.325 -0.25,0.625
3D body: height 0.58, standoff 0.19, extent -0.654,-0.7 0.654,0.7
3D body: height 0.27, standoff 0, extent -0.135,-0.335 0.135,-0.065
3D body: height 0.27, standoff 0, extent 0.211,0.265 0.482,0.535
3D body: height 0.27, standoff 0, extent -0.482,0.265 -0.211,0.535

## ICC_WLCSP9_1P35X1P35_P040 [mm] "MCD-02405"
height 0.66
pads (9):
  round 0.2 smd mask+0.05: A1(-0.4,0.4) A2(0,0.4) A3(0.4,0.4) B1(-0.4,0) B2(0,0) B3(0.4,0) C1(-0.4,-0.4) C2(0,-0.4) C3(0.4,-0.4)
Top Overlay:
  lines w0.12: -0.85,0.26 -0.85,0.86 -0.375,0.86 ; -0.67,-0.675 -0.67,0.675 0.675,0.675 0.675,-0.675 -0.67,-0.675
M14-Top Assembly:
  circle w0.01: c-0.4,0.4 r0.11
  circle w0.01: c0,0.4 r0.11
  circle w0.01: c0.4,0.4 r0.11
  circle w0.01: c-0.4,0 r0.11
  circle w0.01: c0,0 r0.11
  circle w0.01: c0.4,0 r0.11
  circle w0.01: c-0.4,-0.4 r0.11
  circle w0.01: c0,-0.4 r0.11
  circle w0.01: c0.4,-0.4 r0.11
  lines w0.01: -0.675,-0.675 -0.675,0.675 0.675,0.675 0.675,-0.675 -0.675,-0.675
  text "A1" at -0.67,0.28 h0.5
  text "'.Designator'" at -2,-0.5 h0.75
M16-Top Courtyard:
  lines w0.01: -0.875,-0.875 -0.875,0.875 0.875,0.875 0.875,-0.875 -0.875,-0.875
3D body: height 0.22, standoff 0, extent -0.503,0.292 -0.29,0.508
3D body: height 0.22, standoff 0, extent 0.297,0.292 0.51,0.509
3D body: height 0.22, standoff 0, extent -0.103,-0.108 0.11,0.109
3D body: height 0.55, standoff 0.22, extent -0.675,-0.675 0.675,0.675
3D body: height 0.56, standoff 0.55, extent -0.549,0.25 -0.25,0.55
3D body: height 0.22, standoff 0, extent -0.103,0.292 0.11,0.508
3D body: height 0.22, standoff 0, extent -0.503,-0.108 -0.29,0.109
3D body: height 0.22, standoff 0, extent 0.297,-0.108 0.51,0.109
3D body: height 0.22, standoff 0, extent 0.297,-0.508 0.51,-0.291
3D body: height 0.22, standoff 0, extent -0.103,-0.508 0.11,-0.291
3D body: height 0.22, standoff 0, extent -0.503,-0.508 -0.29,-0.291

## ICC_WLCSP11_2P539X2P735_P065 [mm] "MCD-02354"
height 0.6
pads (11):
  round 0.275 smd paste+0 mask+0.05: A1(-0.65,0.975) A2(0,0.975) A3(0.65,0.975) B1(-0.65,0.325) B2(0,0.325) B3(0.65,0.325) C1(-0.65,-0.325) C3(0.65,-0.325) D1(-0.65,-0.975) D2(0,-0.975) D3(0.65,-0.975)
Top Overlay:
  lines w0.12: -1.45,0.85 -1.45,1.55 -0.75,1.55 ; -1.3,-1.4 1.3,-1.4 1.3,1.4 -1.3,1.4 -1.3,-1.4
M14-Top Assembly:
  circle w0.01: c0.65,0.975 r0.14
  circle w0.01: c0,0.975 r0.14
  circle w0.01: c-0.65,0.975 r0.14
  circle w0.01: c-0.65,0.325 r0.14
  circle w0.01: c0,0.325 r0.14
  circle w0.01: c0.65,0.325 r0.14
  circle w0.01: c-0.65,-0.325 r0.14
  circle w0.01: c0.65,-0.325 r0.14
  circle w0.01: c-0.65,-0.975 r0.14
  circle w0.01: c0,-0.975 r0.14
  circle w0.01: c0.65,-0.975 r0.14
  lines w0.01: -1.3,-1.4 1.3,-1.4 1.3,1.4 -1.3,1.4 -1.3,-1.4
  text "'.Designator'" at -2,-0.5 h0.75
  text "A1" at -0.89,0.825 h0.5
M16-Top Courtyard:
  lines w0.01: -1.55,-1.65 1.55,-1.65 1.55,1.65 -1.55,1.65 -1.55,-1.65
3D body: height 0.6, standoff 0.2, extent -1.3,-1.4 1.3,1.4
3D body: height 0.26, standoff -0.02, extent 0.514,0.837 0.786,1.113
3D body: height 0.26, standoff -0.02, extent -0.136,0.837 0.136,1.113
3D body: height 0.61, standoff 0.6, extent -0.799,0.825 -0.5,1.125
3D body: height 0.26, standoff -0.02, extent -0.781,0.837 -0.51,1.113
3D body: height 0.26, standoff -0.02, extent -0.781,0.187 -0.51,0.463
3D body: height 0.26, standoff -0.02, extent -0.136,0.187 0.136,0.463
3D body: height 0.26, standoff -0.02, extent 0.514,0.187 0.786,0.463
3D body: height 0.26, standoff -0.02, extent -0.781,-0.463 -0.51,-0.187
3D body: height 0.26, standoff -0.02, extent 0.514,-0.463 0.786,-0.187
3D body: height 0.26, standoff -0.02, extent -0.781,-1.113 -0.51,-0.837
3D body: height 0.26, standoff -0.02, extent -0.136,-1.113 0.136,-0.837
3D body: height 0.26, standoff -0.02, extent 0.514,-1.113 0.786,-0.837

## ICC_WLCSP12_1P858x1P318_P040 [mm] "MCD-03166"
height 0.612
pads (12):
  round 0.215 smd paste+0 mask+0.04: A1(-0.6,0.4) A2(-0.2,0.4) A3(0.2,0.4) A4(0.6,0.4) B1(-0.6,0) B2(-0.2,0) B3(0.2,0) B4(0.6,0) C1(-0.6,-0.4) C2(-0.2,-0.4) C3(0.2,-0.4) C4(0.6,-0.4)
Top Overlay:
  lines w0.12: -1.07,0.105 -1.07,0.805 -0.37,0.805 ; -0.929,-0.659 -0.929,0.659 0.929,0.659 0.929,-0.659 -0.929,-0.659
M14-Top Assembly:
  circle w0.01: c0.2,0 r0.14
  circle w0.01: c-0.6,0.4 r0.14
  circle w0.01: c-0.6,0 r0.14
  circle w0.01: c-0.6,-0.4 r0.14
  circle w0.01: c-0.2,-0.4 r0.14
  circle w0.01: c-0.2,0 r0.14
  circle w0.01: c-0.2,0.4 r0.14
  circle w0.01: c0.2,-0.4 r0.14
  circle w0.01: c0.2,0.4 r0.14
  circle w0.01: c0.6,-0.4 r0.14
  circle w0.01: c0.6,0 r0.14
  circle w0.01: c0.6,0.4 r0.14
  lines w0.01: -0.929,-0.659 0.929,-0.659 0.929,0.659 -0.929,0.659 -0.929,-0.659
  text "'.Designator'" at -2,-0.5 h0.75
  text "A1" at -0.875,0.25 h0.5
M16-Top Courtyard:
  lines w0.01: -1.175,-0.9 -1.175,0.9 1.175,0.9 1.175,-0.9 -1.175,-0.9
3D body: height 0.26, standoff -0.02, extent 0.062,-0.136 0.338,0.136
3D body: height 0.61, standoff 0.22, extent -0.929,-0.659 0.929,0.659
3D body: height 0.26, standoff -0.02, extent -0.738,0.264 -0.462,0.536
3D body: height 0.26, standoff -0.02, extent -0.738,-0.136 -0.462,0.136
3D body: height 0.62, standoff 0.61, extent -0.75,0.247 -0.45,0.546
3D body: height 0.26, standoff -0.02, extent -0.738,-0.536 -0.462,-0.264
3D body: height 0.26, standoff -0.02, extent -0.338,-0.536 -0.062,-0.264
3D body: height 0.26, standoff -0.02, extent -0.338,-0.136 -0.062,0.136
3D body: height 0.26, standoff -0.02, extent -0.338,0.264 -0.062,0.536
3D body: height 0.26, standoff -0.02, extent 0.062,-0.536 0.338,-0.264
3D body: height 0.26, standoff -0.02, extent 0.062,0.264 0.338,0.536
3D body: height 0.26, standoff -0.02, extent 0.462,-0.536 0.738,-0.264
3D body: height 0.26, standoff -0.02, extent 0.462,-0.136 0.738,0.136
3D body: height 0.26, standoff -0.02, extent 0.462,0.264 0.738,0.536

## ICC_WLCSP20_1P94X2P40_P040 [mm] "MCD-02303"
height 0.59
pads (20):
  round 0.2 smd paste+0.025 mask+0.05: A1(-0.6,0.8) A2(-0.2,0.8) A3(0.2,0.8) A4(0.6,0.8) B1(-0.6,0.4) B2(-0.2,0.4) B3(0.2,0.4) B4(0.6,0.4) C1(-0.6,0) C2(-0.2,0) C3(0.2,0) C4(0.6,0) D1(-0.6,-0.4) D2(-0.2,-0.4) D3(0.2,-0.4) D4(0.6,-0.4) E1(-0.6,-0.8) E2(-0.2,-0.8) E3(0.2,-0.8) E4(0.6,-0.8)
Top Overlay:
  lines w0.12: -1.125,0.625 -1.125,1.35 -0.4,1.35 ; -0.98,-1.21 0.98,-1.21 0.98,1.21 -0.98,1.21 -0.98,-1.21
M14-Top Assembly:
  circle w0.01: c0.6,0.8 r0.14
  circle w0.01: c0.2,0.8 r0.14
  circle w0.01: c-0.2,0.8 r0.14
  circle w0.01: c-0.6,0.8 r0.14
  circle w0.01: c-0.6,0.4 r0.14
  circle w0.01: c-0.2,0.4 r0.14
  circle w0.01: c0.2,0.4 r0.14
  circle w0.01: c0.6,0.4 r0.14
  circle w0.01: c-0.6,0 r0.14
  circle w0.01: c-0.2,0 r0.14
  circle w0.01: c0.2,0 r0.14
  circle w0.01: c0.6,0 r0.14
  circle w0.01: c-0.6,-0.4 r0.14
  circle w0.01: c-0.2,-0.4 r0.14
  circle w0.01: c0.2,-0.4 r0.14
  circle w0.01: c0.6,-0.4 r0.14
  circle w0.01: c-0.6,-0.8 r0.14
  circle w0.01: c-0.2,-0.8 r0.14
  circle w0.01: c0.2,-0.8 r0.14
  circle w0.01: c0.6,-0.8 r0.14
  lines w0.01: -0.98,-1.21 -0.98,1.21 0.98,1.21 0.98,-1.21 -0.98,-1.21
  text "'.Designator'" at -2,-0.5 h0.75
  text "A1" at -0.845,0.645 h0.5
M16-Top Courtyard:
  lines w0.01: -1.25,0.525 -1.18,0.455 -1.18,0.355 -1.18,-1.41 1.18,-1.41 1.18,0.241 1.18,1.41 -0.125,1.41 -0.21,1.41 -0.275,1.475 -0.325,1.475 -1.25,1.475 -1.25,0.525
3D body: height 0.26, standoff -0.02, extent 0.469,0.662 0.74,0.938
3D body: height 0.26, standoff -0.02, extent 0.069,0.662 0.34,0.938
3D body: height 0.26, standoff -0.02, extent -0.331,0.662 -0.06,0.938
3D body: height 0.6, standoff 0.59, extent -0.749,0.65 -0.45,0.95
3D body: height 0.59, standoff 0.22, extent -0.98,-1.21 0.98,1.21
3D body: height 0.26, standoff -0.02, extent -0.731,0.662 -0.46,0.938
3D body: height 0.26, standoff -0.02, extent -0.731,0.262 -0.46,0.538
3D body: height 0.26, standoff -0.02, extent -0.331,0.262 -0.06,0.538
3D body: height 0.26, standoff -0.02, extent 0.069,0.262 0.34,0.538
3D body: height 0.26, standoff -0.02, extent 0.469,0.262 0.74,0.538
3D body: height 0.26, standoff -0.02, extent -0.731,-0.138 -0.46,0.138
3D body: height 0.26, standoff -0.02, extent -0.331,-0.138 -0.06,0.138
3D body: height 0.26, standoff -0.02, extent 0.069,-0.138 0.34,0.138
3D body: height 0.26, standoff -0.02, extent 0.469,-0.138 0.74,0.138
3D body: height 0.26, standoff -0.02, extent -0.731,-0.538 -0.46,-0.262
3D body: height 0.26, standoff -0.02, extent -0.331,-0.538 -0.06,-0.262
3D body: height 0.26, standoff -0.02, extent 0.069,-0.538 0.34,-0.262
3D body: height 0.26, standoff -0.02, extent 0.469,-0.538 0.74,-0.262
3D body: height 0.26, standoff -0.02, extent -0.731,-0.938 -0.46,-0.662
3D body: height 0.26, standoff -0.02, extent -0.331,-0.938 -0.06,-0.662
3D body: height 0.26, standoff -0.02, extent 0.069,-0.938 0.34,-0.662
3D body: height 0.26, standoff -0.02, extent 0.469,-0.938 0.74,-0.662

## ICC_WLCSP30_2P537X2P114_P040 [mm]
height 0.6
pads (30):
  round 0.2 smd paste+0.025 mask+0.05: A1(-0.8,1) A2(-0.4,1) A3(0,1) A4(0.4,1) A5(0.8,1) B1(-0.8,0.6) B2(-0.4,0.6) B3(0,0.6) B4(0.4,0.6) B5(0.8,0.6) C1(-0.8,0.2) C2(-0.4,0.2) C3(0,0.2) C4(0.4,0.2) C5(0.8,0.2) D1(-0.8,-0.2) D2(-0.4,-0.2) D3(0,-0.2) D4(0.4,-0.2) D5(0.8,-0.2) E1(-0.8,-0.6) E2(-0.4,-0.6) E3(0,-0.6) E4(0.4,-0.6) E5(0.8,-0.6) F1(-0.8,-1) F2(-0.4,-1) F3(0,-1) F4(0.4,-1) F5(0.8,-1)
Top Overlay:
  lines w0.12: -1.25,0.75 -1.25,1.475 -0.525,1.475 ; -1.057,-1.268 -1.057,1.268 1.057,1.268 1.057,-1.268 -1.057,-1.268
M14-Top Assembly:
  circle w0.01: c0.8,-1 r0.14
  circle w0.01: c0.4,-1 r0.14
  circle w0.01: c0,-1 r0.14
  circle w0.01: c-0.4,-1 r0.14
  circle w0.01: c-0.8,-1 r0.14
  circle w0.01: c0.8,-0.6 r0.14
  circle w0.01: c0.8,-0.2 r0.14
  circle w0.01: c0.8,0.2 r0.14
  circle w0.01: c0.8,0.6 r0.14
  circle w0.01: c0.8,1 r0.14
  circle w0.01: c0.4,-0.6 r0.14
  circle w0.01: c0,-0.6 r0.14
  circle w0.01: c-0.4,-0.6 r0.14
  circle w0.01: c-0.8,-0.6 r0.14
  circle w0.01: c0.4,-0.2 r0.14
  circle w0.01: c0,-0.2 r0.14
  circle w0.01: c-0.4,-0.2 r0.14
  circle w0.01: c-0.8,-0.2 r0.14
  circle w0.01: c0.4,0.2 r0.14
  circle w0.01: c0,0.2 r0.14
  circle w0.01: c-0.4,0.2 r0.14
  circle w0.01: c-0.8,0.2 r0.14
  circle w0.01: c0.4,0.6 r0.14
  circle w0.01: c0,0.6 r0.14
  circle w0.01: c-0.4,0.6 r0.14
  circle w0.01: c-0.8,0.6 r0.14
  circle w0.01: c-0.8,1 r0.14
  circle w0.01: c-0.4,1 r0.14
  circle w0.01: c0,1 r0.14
  circle w0.01: c0.4,1 r0.14
  lines w0.01: -1.057,-1.268 1.057,-1.268 1.057,1.268 -1.057,1.268 -1.057,-1.268
  text "A1" at -1.075,0.85 h0.5
  text "'.Designator'" at -2,-0.5 h0.75
M16-Top Courtyard:
  lines w0.01: -1.3,-1.525 1.3,-1.525 1.3,1.525 -1.3,1.525 -1.3,-1.525
3D body: height 0.26, standoff -0.02, extent 0.669,-1.138 0.94,-0.862
3D body: height 0.26, standoff -0.02, extent 0.269,-1.138 0.54,-0.862
3D body: height 0.26, standoff -0.02, extent -0.131,-1.138 0.14,-0.862
3D body: height 0.26, standoff -0.02, extent -0.531,-1.138 -0.26,-0.862
3D body: height 0.26, standoff -0.02, extent -0.931,-1.138 -0.66,-0.862
3D body: height 0.26, standoff -0.02, extent 0.669,-0.738 0.94,-0.462
3D body: height 0.26, standoff -0.02, extent 0.669,-0.338 0.94,-0.062
3D body: height 0.26, standoff -0.02, extent 0.669,0.062 0.94,0.338
3D body: height 0.26, standoff -0.02, extent 0.669,0.462 0.94,0.738
3D body: height 0.26, standoff -0.02, extent 0.669,0.862 0.94,1.138
3D body: height 0.26, standoff -0.02, extent 0.269,-0.738 0.54,-0.462
3D body: height 0.26, standoff -0.02, extent -0.131,-0.738 0.14,-0.462
3D body: height 0.26, standoff -0.02, extent -0.531,-0.738 -0.26,-0.462
3D body: height 0.26, standoff -0.02, extent -0.931,-0.738 -0.66,-0.462
3D body: height 0.26, standoff -0.02, extent 0.269,-0.338 0.54,-0.062
3D body: height 0.26, standoff -0.02, extent -0.131,-0.338 0.14,-0.062
3D body: height 0.26, standoff -0.02, extent -0.531,-0.338 -0.26,-0.062
3D body: height 0.26, standoff -0.02, extent -0.931,-0.338 -0.66,-0.062
3D body: height 0.26, standoff -0.02, extent 0.269,0.062 0.54,0.338
3D body: height 0.26, standoff -0.02, extent -0.131,0.062 0.14,0.338
3D body: height 0.26, standoff -0.02, extent -0.531,0.062 -0.26,0.338
3D body: height 0.26, standoff -0.02, extent -0.931,0.062 -0.66,0.338
3D body: height 0.26, standoff -0.02, extent 0.269,0.462 0.54,0.738
3D body: height 0.26, standoff -0.02, extent -0.131,0.462 0.14,0.738
3D body: height 0.26, standoff -0.02, extent -0.531,0.462 -0.26,0.738
3D body: height 0.26, standoff -0.02, extent -0.931,0.462 -0.66,0.738
3D body: height 0.26, standoff -0.02, extent -0.931,0.862 -0.66,1.138
3D body: height 0.6, standoff 0.22, extent -1.057,-1.268 1.057,1.268
3D body: height 0.6, standoff 0.59, extent -0.949,0.85 -0.65,1.15
3D body: height 0.26, standoff -0.02, extent -0.531,0.862 -0.26,1.138
3D body: height 0.26, standoff -0.02, extent -0.131,0.862 0.14,1.138
3D body: height 0.26, standoff -0.02, extent 0.269,0.862 0.54,1.138

## ICC_WLCSP33_2P12X2P49_P035 [mm] "MCD-02435"
height 0.5
pads (33):
  round 0.2 smd paste+0.019 mask+0.038: A2(-0.456,0.875) A4(0.152,0.875) A6(0.76,0.875) B1(-0.76,0.7) B3(-0.152,0.7) B5(0.456,0.7) C2(-0.456,0.525) C4(0.152,0.525) C6(0.76,0.525) D1(-0.76,0.35) D3(-0.152,0.35) D5(0.456,0.35) E2(-0.456,0.175) E4(0.152,0.175) E6(0.76,0.175) F1(-0.76,0) F3(-0.152,0) F5(0.456,0) G2(-0.456,-0.175) G4(0.152,-0.175) G6(0.76,-0.175) H1(-0.76,-0.35) H3(-0.152,-0.35) H5(0.456,-0.35) J2(-0.456,-0.525) J4(0.152,-0.525) J6(0.76,-0.525) K1(-0.76,-0.7) K3(-0.152,-0.7) K5(0.456,-0.7) L2(-0.456,-0.875) L4(0.152,-0.875) L6(0.76,-0.875)
Top Overlay:
  lines w0.12: -1.25,0.525 -1.25,1.475 -0.325,1.475 ; -1.06,-1.245 -1.06,1.245 1.06,1.245 1.06,-1.245 -1.06,-1.245
M14-Top Assembly:
  circle w0.01: c-0.76,-0.7 r0.125
  circle w0.01: c-0.76,-0.35 r0.125
  circle w0.01: c-0.76,0 r0.125
  circle w0.01: c-0.76,0.35 r0.125
  circle w0.01: c-0.76,0.7 r0.125
  circle w0.01: c-0.456,-0.875 r0.125
  circle w0.01: c-0.456,-0.525 r0.125
  circle w0.01: c-0.456,-0.175 r0.125
  circle w0.01: c-0.456,0.175 r0.125
  circle w0.01: c-0.456,0.525 r0.125
  circle w0.01: c-0.456,0.875 r0.125
  circle w0.01: c-0.152,-0.7 r0.125
  circle w0.01: c-0.152,-0.35 r0.125
  circle w0.01: c-0.152,0 r0.125
  circle w0.01: c-0.152,0.35 r0.125
  circle w0.01: c-0.152,0.7 r0.125
  circle w0.01: c0.152,-0.875 r0.125
  circle w0.01: c0.152,-0.525 r0.125
  circle w0.01: c0.152,-0.175 r0.125
  circle w0.01: c0.152,0.175 r0.125
  circle w0.01: c0.152,0.525 r0.125
  circle w0.01: c0.152,0.875 r0.125
  circle w0.01: c0.76,-0.875 r0.125
  circle w0.01: c0.76,-0.525 r0.125
  circle w0.01: c0.76,-0.175 r0.125
  circle w0.01: c0.76,0.175 r0.125
  circle w0.01: c0.76,0.525 r0.125
  circle w0.01: c0.76,0.875 r0.125
  circle w0.01: c0.456,-0.7 r0.125
  circle w0.01: c0.456,-0.35 r0.125
  circle w0.01: c0.456,0 r0.125
  circle w0.01: c0.456,0.35 r0.125
  circle w0.01: c0.456,0.7 r0.125
  lines w0.01: -1.06,-1.245 1.06,-1.245 1.06,1.245 -1.06,1.245 -1.06,-1.245
  text "A2" at -0.704,0.73 h0.5
  text "'.Designator'" at -2,-0.5 h0.75
M16-Top Courtyard:
  lines w0.01: -1.33,0.499 -1.33,1.553 -0.278,1.553 -0.17,1.445 1.26,1.445 1.26,-1.445 -1.26,-1.445 -1.26,0.429 -1.33,0.499
3D body: height 0.51, standoff 0.5, extent -0.749,0.65 -0.45,0.95
3D body: height 0.24, standoff -0.02, extent -0.573,0.752 -0.331,0.998
3D body: height 0.5, standoff 0.17, extent -1.06,-1.245 1.06,1.245
3D body: height 0.24, standoff -0.02, extent 0.035,0.752 0.277,0.998
3D body: height 0.24, standoff -0.02, extent 0.643,0.752 0.885,0.998
3D body: height 0.24, standoff -0.02, extent 0.339,0.577 0.581,0.823
3D body: height 0.24, standoff -0.02, extent -0.269,0.577 -0.027,0.823
3D body: height 0.24, standoff -0.02, extent -0.877,0.577 -0.635,0.823
3D body: height 0.24, standoff -0.02, extent -0.573,0.402 -0.331,0.648
3D body: height 0.24, standoff -0.02, extent 0.035,0.402 0.277,0.648
3D body: height 0.24, standoff -0.02, extent 0.643,0.402 0.885,0.648
3D body: height 0.24, standoff -0.02, extent 0.339,0.227 0.581,0.473
3D body: height 0.24, standoff -0.02, extent -0.269,0.227 -0.027,0.473
3D body: height 0.24, standoff -0.02, extent -0.877,0.227 -0.635,0.473
3D body: height 0.24, standoff -0.02, extent -0.573,0.052 -0.331,0.298
3D body: height 0.24, standoff -0.02, extent 0.035,0.052 0.277,0.298
3D body: height 0.24, standoff -0.02, extent 0.643,0.052 0.885,0.298
3D body: height 0.24, standoff -0.02, extent 0.339,-0.123 0.581,0.123
3D body: height 0.24, standoff -0.02, extent -0.269,-0.123 -0.027,0.123
3D body: height 0.24, standoff -0.02, extent -0.877,-0.123 -0.635,0.123
3D body: height 0.24, standoff -0.02, extent -0.573,-0.298 -0.331,-0.052
3D body: height 0.24, standoff -0.02, extent 0.035,-0.298 0.277,-0.052
3D body: height 0.24, standoff -0.02, extent 0.643,-0.298 0.885,-0.052
3D body: height 0.24, standoff -0.02, extent 0.339,-0.473 0.581,-0.227
3D body: height 0.24, standoff -0.02, extent -0.269,-0.473 -0.027,-0.227
3D body: height 0.24, standoff -0.02, extent -0.877,-0.473 -0.635,-0.227
3D body: height 0.24, standoff -0.02, extent -0.573,-0.648 -0.331,-0.402
3D body: height 0.24, standoff -0.02, extent 0.035,-0.648 0.277,-0.402
3D body: height 0.24, standoff -0.02, extent 0.643,-0.648 0.885,-0.402
3D body: height 0.24, standoff -0.02, extent 0.339,-0.823 0.581,-0.577
3D body: height 0.24, standoff -0.02, extent -0.269,-0.823 -0.027,-0.577
3D body: height 0.24, standoff -0.02, extent -0.877,-0.823 -0.635,-0.577
3D body: height 0.24, standoff -0.02, extent -0.573,-0.998 -0.331,-0.752
3D body: height 0.24, standoff -0.02, extent 0.035,-0.998 0.277,-0.752
3D body: height 0.24, standoff -0.02, extent 0.643,-0.998 0.885,-0.752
